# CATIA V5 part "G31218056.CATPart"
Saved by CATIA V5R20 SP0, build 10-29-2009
Part number: G31218056
Revision: 9
Definition: design
Nomenclature: G31218056
Source: made
Description: NOT SPECIFIED
Bounding box of the stored display mesh (mm): x -8 to 56, y -15.5 to 15.5, z -15.5 to 15.5
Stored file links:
  C:\Users\Raffaele\Desktop\3D X SITO CF\BOLEX\23-BUSH REF 312\G31218056.CATPart

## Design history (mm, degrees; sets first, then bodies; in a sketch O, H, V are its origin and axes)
Body1 "MANIFOLD_SOLID_BREP #14787" (main body)
  Solid1: solid without history
Body2 "MANIFOLD_SOLID_BREP #14934"
  Solid2: solid without history
Body3 "MANIFOLD_SOLID_BREP #15081"
  Solid3: solid without history
Body4 "MANIFOLD_SOLID_BREP #15228"
  Solid4: solid without history
Body5 "MANIFOLD_SOLID_BREP #15375"
  Solid5: solid without history
Body6 "MANIFOLD_SOLID_BREP #15522"
  Solid6: solid without history
Body7 "MANIFOLD_SOLID_BREP #15669"
  Solid7: solid without history
Body8 "MANIFOLD_SOLID_BREP #15818"
  Solid8: solid without history
Body9 "MANIFOLD_SOLID_BREP #15967"
  Solid9: solid without history
Body10 "MANIFOLD_SOLID_BREP #16114"
  Solid10: solid without history
Body11 "MANIFOLD_SOLID_BREP #16261"
  Solid11: solid without history
Body12 "MANIFOLD_SOLID_BREP #16408"
  Solid12: solid without history
Body13 "MANIFOLD_SOLID_BREP #16555"
  Solid13: solid without history
Body14 "MANIFOLD_SOLID_BREP #16704"
  Solid14: solid without history
Body15 "MANIFOLD_SOLID_BREP #16853"
  Solid15: solid without history
Body16 "MANIFOLD_SOLID_BREP #17000"
  Solid16: solid without history
Body17 "MANIFOLD_SOLID_BREP #17147"
  Solid17: solid without history
Body18 "MANIFOLD_SOLID_BREP #17294"
  Solid18: solid without history
Body19 "MANIFOLD_SOLID_BREP #17441"
  Solid19: solid without history
Body20 "MANIFOLD_SOLID_BREP #17588"
  Solid20: solid without history
Body21 "MANIFOLD_SOLID_BREP #17735"
  Solid21: solid without history
Body22 "MANIFOLD_SOLID_BREP #17882"
  Solid22: solid without history
Body23 "MANIFOLD_SOLID_BREP #18029"
  Solid23: solid without history
Body24 "MANIFOLD_SOLID_BREP #18176"
  Solid24: solid without history
Body25 "MANIFOLD_SOLID_BREP #18323"
  Solid25: solid without history
Body26 "MANIFOLD_SOLID_BREP #18470"
  Solid26: solid without history
Body27 "MANIFOLD_SOLID_BREP #18619"
  Solid27: solid without history
Body28 "MANIFOLD_SOLID_BREP #18766"
  Solid28: solid without history
Body29 "MANIFOLD_SOLID_BREP #18913"
  Solid29: solid without history
Body30 "MANIFOLD_SOLID_BREP #19062"
  Solid30: solid without history
Body31 "MANIFOLD_SOLID_BREP #19209"
  Solid31: solid without history
Body32 "MANIFOLD_SOLID_BREP #19356"
  Solid32: solid without history
Body33 "MANIFOLD_SOLID_BREP #19503"
  Solid33: solid without history
Body34 "MANIFOLD_SOLID_BREP #19650"
  Solid34: solid without history
Body35 "MANIFOLD_SOLID_BREP #19797"
  Solid35: solid without history
Body36 "MANIFOLD_SOLID_BREP #19944"
  Solid36: solid without history
Body37 "MANIFOLD_SOLID_BREP #20091"
  Solid37: solid without history
Body38 "MANIFOLD_SOLID_BREP #20238"
  Solid38: solid without history
Body39 "MANIFOLD_SOLID_BREP #20385"
  Solid39: solid without history
Body40 "MANIFOLD_SOLID_BREP #20532"
  Solid40: solid without history
Body41 "MANIFOLD_SOLID_BREP #20679"
  Solid41: solid without history
Body42 "MANIFOLD_SOLID_BREP #20826"
  Solid42: solid without history
Body43 "MANIFOLD_SOLID_BREP #20975"
  Solid43: solid without history
Body44 "MANIFOLD_SOLID_BREP #21122"
  Solid44: solid without history
Body45 "MANIFOLD_SOLID_BREP #21269"
  Solid45: solid without history
Body46 "MANIFOLD_SOLID_BREP #21418"
  Solid46: solid without history
Body47 "MANIFOLD_SOLID_BREP #21565"
  Solid47: solid without history
Body48 "MANIFOLD_SOLID_BREP #21712"
  Solid48: solid without history
Body49 "MANIFOLD_SOLID_BREP #21859"
  Solid49: solid without history
Body50 "MANIFOLD_SOLID_BREP #22006"
  Solid50: solid without history
Body51 "MANIFOLD_SOLID_BREP #22153"
  Solid51: solid without history
Body52 "MANIFOLD_SOLID_BREP #22300"
  Solid52: solid without history
Body53 "MANIFOLD_SOLID_BREP #22447"
  Solid53: solid without history
Body54 "MANIFOLD_SOLID_BREP #22594"
  Solid54: solid without history
Body55 "MANIFOLD_SOLID_BREP #22741"
  Solid55: solid without history
Body56 "MANIFOLD_SOLID_BREP #22888"
  Solid56: solid without history
Body57 "MANIFOLD_SOLID_BREP #23035"
  Solid57: solid without history
Body58 "MANIFOLD_SOLID_BREP #23182"
  Solid58: solid without history
Body59 "MANIFOLD_SOLID_BREP #23331"
  Solid59: solid without history
Body60 "MANIFOLD_SOLID_BREP #23478"
  Solid60: solid without history
Body61 "MANIFOLD_SOLID_BREP #23625"
  Solid61: solid without history
Body62 "MANIFOLD_SOLID_BREP #23774"
  Solid62: solid without history
Body63 "MANIFOLD_SOLID_BREP #23921"
  Solid63: solid without history
Body64 "MANIFOLD_SOLID_BREP #24068"
  Solid64: solid without history
Body65 "MANIFOLD_SOLID_BREP #24215"
  Solid65: solid without history
Body66 "MANIFOLD_SOLID_BREP #24362"
  Solid66: solid without history
Body67 "MANIFOLD_SOLID_BREP #24509"
  Solid67: solid without history
Body68 "MANIFOLD_SOLID_BREP #24656"
  Solid68: solid without history
Body69 "MANIFOLD_SOLID_BREP #24803"
  Solid69: solid without history
Body70 "MANIFOLD_SOLID_BREP #24950"
  Solid70: solid without history
Body71 "MANIFOLD_SOLID_BREP #25097"
  Solid71: solid without history
Body72 "MANIFOLD_SOLID_BREP #25244"
  Solid72: solid without history
Body73 "MANIFOLD_SOLID_BREP #25391"
  Solid73: solid without history
Body74 "MANIFOLD_SOLID_BREP #25538"
  Solid74: solid without history
Body75 "MANIFOLD_SOLID_BREP #25685"
  Solid75: solid without history
Body76 "MANIFOLD_SOLID_BREP #25834"
  Solid76: solid without history
Body77 "MANIFOLD_SOLID_BREP #25983"
  Solid77: solid without history
Body78 "MANIFOLD_SOLID_BREP #26130"
  Solid78: solid without history
Body79 "MANIFOLD_SOLID_BREP #26277"
  Solid79: solid without history
Body80 "MANIFOLD_SOLID_BREP #26424"
  Solid80: solid without history
Body81 "MANIFOLD_SOLID_BREP #26571"
  Solid81: solid without history
Body82 "MANIFOLD_SOLID_BREP #26720"
  Solid82: solid without history
Body83 "MANIFOLD_SOLID_BREP #26869"
  Solid83: solid without history
Body84 "MANIFOLD_SOLID_BREP #27016"
  Solid84: solid without history
Body85 "MANIFOLD_SOLID_BREP #27163"
  Solid85: solid without history
Body86 "MANIFOLD_SOLID_BREP #27310"
  Solid86: solid without history
Body87 "MANIFOLD_SOLID_BREP #27457"
  Solid87: solid without history
Body88 "MANIFOLD_SOLID_BREP #27604"
  Solid88: solid without history
Body89 "MANIFOLD_SOLID_BREP #27751"
  Solid89: solid without history
Body90 "MANIFOLD_SOLID_BREP #27898"
  Solid90: solid without history
Body91 "MANIFOLD_SOLID_BREP #28045"
  Solid91: solid without history
Body92 "MANIFOLD_SOLID_BREP #28192"
  Solid92: solid without history
Body93 "MANIFOLD_SOLID_BREP #28339"
  Solid93: solid without history
Body94 "MANIFOLD_SOLID_BREP #28486"
  Solid94: solid without history
Body95 "MANIFOLD_SOLID_BREP #28633"
  Solid95: solid without history
Body96 "MANIFOLD_SOLID_BREP #28780"
  Solid96: solid without history
Body97 "MANIFOLD_SOLID_BREP #28927"
  Solid97: solid without history
Body98 "MANIFOLD_SOLID_BREP #29074"
  Solid98: solid without history
Body99 "MANIFOLD_SOLID_BREP #29221"
  Solid99: solid without history
Body100 "MANIFOLD_SOLID_BREP #29368"
  Solid100: solid without history
Body101 "MANIFOLD_SOLID_BREP #29515"
  Solid101: solid without history
Body102 "MANIFOLD_SOLID_BREP #29662"
  Solid102: solid without history
Body103 "MANIFOLD_SOLID_BREP #29809"
  Solid103: solid without history
Body104 "MANIFOLD_SOLID_BREP #29956"
  Solid104: solid without history
Body105 "MANIFOLD_SOLID_BREP #30103"
  Solid105: solid without history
